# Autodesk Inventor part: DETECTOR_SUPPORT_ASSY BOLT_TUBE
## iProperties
Shininess: 64.0
Length Units: 11272
Angle Units: 11279
Time Units: 11290
Mass Units: 11286
Length Display Precision: 3
Angle Display Precision: 2
Compacted: True
Part Number: DETECTOR_SUPPORT_ASSY BOLT_TUBE
Document SubType Name: Modeling
Created: 2004-08
Designer: John Blackburn
Material: MILD_STEEL
Manufacturer: Standard
Standards Organization: Custom
Density: 0.0
Volumn: 0.0
Area: 0.0
PropertySet Name: Model Information
Control State: 0
Master: False
Checked Out: False
Author: John Blackburn
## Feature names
1. ExtrusionBlind1
2. ExtrusionBlind2
